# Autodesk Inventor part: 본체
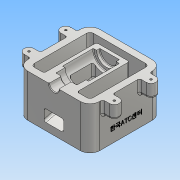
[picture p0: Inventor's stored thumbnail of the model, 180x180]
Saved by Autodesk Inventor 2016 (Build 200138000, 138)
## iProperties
Created: 2018-01
Part Number: 본체
Material: 알루미늄 6061
Document SubType Name: Modeling
Designer: Administrator
Density: 2.7 g/cm^3
Appearance: 알루미늄 - 평지
Mass: 995.367 g
Surface Area: 835.099 cm^2
Volume: 368.654 cm^3
Author: Administrator
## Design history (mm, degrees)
sketch "스케치1"
  geometry: L1 (-55, 55)-(55, 55); L2 (55, 55)-(55, -55); L3 (55, -55)-(-55, -55); L4 (-55, -55)-(-55, 55); L5 (-55, 55)-(55, -55); L6 (55, 55)-(-55, -55); 1 further point
  constraints: 12 end point, 2 midpoint, 2 parallel, 1 horizontal, 1 perpendicular
  dimensions: "d0" = 110 distance of L2.end L3.end; "d1" = 110 distance of L1.end L2.end
extrude "돌출1" new body sketch "스케치1" distance "d2" = 65; taper "d3" = 0 deg
feature "쉘1" dims "d4" = 10
sketch "스케치2"
  geometry: L1 (55, 55)-(-55, 55) reference; L2 (-45, -45)-(45, -45) reference; L3 (-25, 35)-(25, 35); L4 (25, 35)-(25, -45); L5 (25, -45)-(-25, -45); L6 (-25, -45)-(-25, 35); 2 further points
  constraints: 8 end point, 2 parallel, 1 horizontal, 1 midpoint, 1 perpendicular, 1 point on line, 1 vertical alignment
  dimensions: "d5" = 50 distance between parallel lines of L6 L4; "d6" = 20 distance between parallel lines of L3 L1
extrude "돌출2" join sketch "스케치2" distance "d7" = 65; taper "d8" = 0 deg
sketch "스케치3"
  geometry: L1 (-55, 0)-(55, 0) reference; L2 (-45, 0)-(-45, 8.564); L3 (-45, 8.564)-(35, 30); L4 (35, 65)-(35, 0) reference; L5 (-55, 0)-(-55, 65) reference; 1 further point
  constraints: 4 end point, 2 point on line, 1 vertical
  dimensions: "d9" = 30 distance from line of L1 L3.end; "d10" = 105 deg angle of L2 L3; "d11" = 10 distance between parallel lines of L5 L2
extrude "돌출3" cut sketch "스케치3" stored distance "d12" = 50; taper "d13" = 0 deg
sketch "스케치4"
  geometry: L1 (25, 35)-(-25, 35) reference; L2 (0, 35)-(0, -55); L3 (55, -55)-(-55, -55) reference; L4 (0, -55)-(-7.5, -55); L5 (-7.5, -36)-(-16, -36); L6 (-16, -36)-(-16, -22); L7 (-16, -22)-(-20, -22); L8 (-20, -22)-(-20, 25); L9 (-20, 25)-(-15, 25); L10 (-15, 25)-(-15, 30); L11 (-15, 30)-(0, 30); L12 (-7.5, -55)-(-7.5, -36); L13 (0, -55)-(-7.5, -55); 1 further point
  constraints: 22 end point, 6 perpendicular, 2 midpoint, 2 point on line, 1 collinear, 1 horizontal, 1 vertical
  dimensions: "d14" = 40 diameter of L8 L2; "d15" = 15 diameter of L12 L2; "d16" = 32 diameter of L6 L2; "d17" = 19 distance of L4.end L5.start; "d18" = 14 distance of L5.end L6.end; "d19" = 47 distance of L7.end L8.end; "d20" = 5 distance of L9.end L10.end; "d21" = 30 diameter of L10 L2
revolve "회전1" sketch "스케치4" stored, may be unused: angle "d22" = 90 deg
sketch "스케치5"
  geometry: L1 (-55, 55)-(-55, -55) reference; L2 (-55, -55)-(-7.5, -55) reference; L3 (-55, -20.5)-(-65, -20.5); L4 (-65, -20.5)-(-65, -35.5); L5 (-65, -35.5)-(-55, -35.5); L6 (-55, -35.5)-(-55, -20.5); A1 r 7.5 centre (-65, -28) between (-65, -20.5) and (-65, -35.5); 1 further point
  constraints: 8 end point, 2 parallel, 2 point on circle, 1 centre point, 1 horizontal, 1 midpoint, 1 perpendicular, 1 point on line
  dimensions: "d23" = 27 distance from line of L2 A1.centre; "d24" = 10 distance from line of L1 A1.centre; "d25" = 7.5 radius of A1
extrude "돌출4" join sketch "스케치5" distance "d26" = 20; taper "d27" = 0 deg
sketch "스케치6"
  geometry: A1 r 7.5 centre (-65, -28) between (-65, -20.5) and (-65, -35.5) reference; 2 further points
  constraints: 1 coincident
hole "구멍1" sketch "스케치6" at (-65, -28) diameter "d28" = 3.242; stored, may be unused: countersink angle "d32" = 90 deg, drill point angle "d34" = 118 deg; dims "d29" = 9, "d30" = 4, "d31" = 2, "d33" = 11
sketch "스케치7"
  geometry: L1 (-55, 11.061)-(20, 31.157); L2 (-22, 45)-(25, 45) reference; L3 (-55, 0)-(-55, 65) reference; L4 (-55, 29.061)-(-17, 39.243); L5 (35, 30)-(-45, 8.564) reference; L6 (45, 0)-(-45, 0) reference; L7 (25, 45)-(25, 65) reference; L8 (-17, 39.243)-(-17, 67.919); L9 (20, 31.157)-(20, 67.919); L10 (20, 67.919)-(-17, 67.919); 1 further point
  constraints: 10 end point, 2 parallel, 2 point on line, 2 vertical, 1 perpendicular
  dimensions: "d38" = 18 distance of L1.start L4.start; "d39" = 5 distance between parallel lines of L5 L1; "d40" = 30 distance from line of L6 L5.start (derived); "d43" = 37 distance between parallel lines of L9 L8; "d44" = 5 distance between parallel lines of L7 L9
extrude "돌출5" cut sketch "스케치7" stored distance "d45" = 30; taper "d46" = 0 deg
sketch "스케치8"
  geometry: L1 (0, 0)-(-65, 0) reference; L2 (0, 110)-(0, 0) reference; 2 further points
  constraints: 1 other
  dimensions: "d47" = 55 distance from line of L1 point (-20, 55); "d48" = 20 distance from line of L2 point (-20, 55)
feature "엠보싱1" sketch "스케치8" dims "d0" = 110, "d1" = 110, "d49" = 0.5, "d50" = 0
fillet "모깎기1" dims "d51" = 15, "d52" = 5
fillet "모깎기6" dims "d57" = 3
fillet "모깎기7" dims "d58" = 3
fillet "모깎기11" dims "d68" = 3
fillet "모깎기12" dims "d69" = 3
fillet "모깎기13" dims "d70" = 1
chamfer "모따기3" distance "d71" = 1; stored, may be unused: second distance "d72" = 2, angle "d73" = 45 deg
fillet "모깎기14" dims "d74" = 3
node "솔리드1"
pattern_linear "직사각형 패턴1" dims "d37" = 56
mirror "대칭1"
